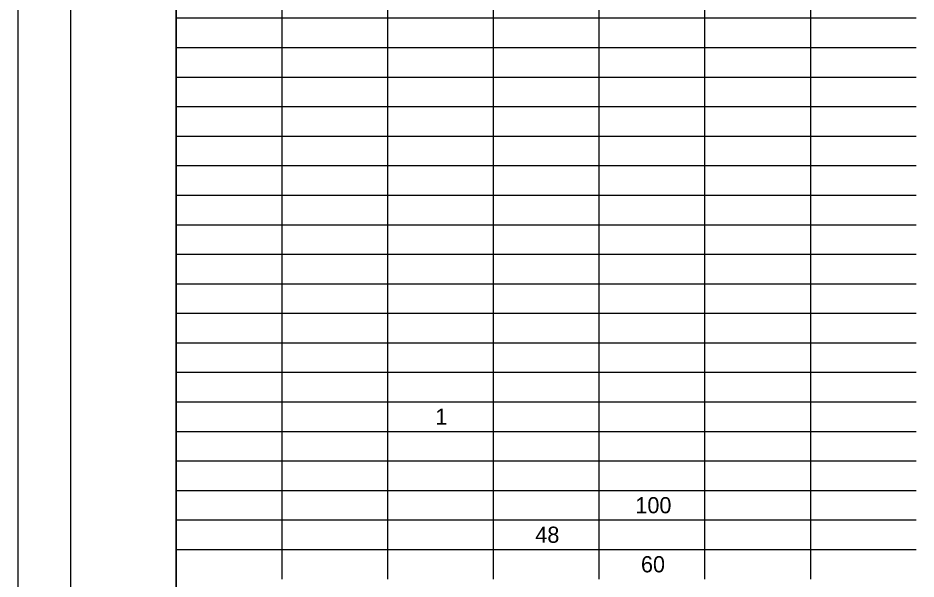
# Model space of a CAD drawing. Extents: x 0 to 34, y 0 to 22.
# Drawn here: x 0 to 8.52, y 11.42 to 16.74 of the extents above; entities that cross this region are included whole.
import ezdxf

# ---------------------------------------------------------------- set-up
doc = ezdxf.new("R2010")
doc.units = 0
for name, color, linetype in [('SH_Border', 7, 'Continuous'), ('SH_Cut_Line', 7, 'Continuous'), ('SH_Text', 7, 'Continuous')]:
    doc.layers.add(name, color=color, linetype=linetype)

msp = doc.modelspace()

# ---------------------------------------------------------------- linework, layer by layer
at = {"layer": 'SH_Border'}
for points in [[(0.5, 21.5), (1.5, 21.5), (1.5, 0.5), (0.5, 0.5)], [(1.5, 21.5), (33.5, 21.5), (33.5, 0.5), (1.5, 0.5)]]:
    msp.add_lwpolyline(points, close=True, dxfattribs=at)
at = {"layer": 'SH_Cut_Line'}
msp.add_lwpolyline([(0, 0), (34, 0), (34, 22), (0, 22)], close=True, dxfattribs=at)
at = {"layer": 'SH_Text'}
for p, q in [((1.5, 17.0199), (1.5, 16.7399)), ((2.5027, 17.0199), (2.5027, 16.7399)), ((3.5053, 17.0199), (3.5053, 16.7399)), ((4.508, 17.0199), (4.508, 16.7399)), ((5.5106, 17.0199), (5.5106, 16.7399)), ((6.5133, 17.0199), (6.5133, 16.7399)), ((7.516, 17.0199), (7.516, 16.7399)), ((1.5, 16.7399), (2.5027, 16.7399)), ((1.5, 16.7399), (1.5, 16.1799)), ((2.5027, 16.7399), (3.5053, 16.7399)), ((2.5027, 16.7399), (2.5027, 16.1799)), ((3.5053, 16.7399), (4.508, 16.7399)), ((3.5053, 16.7399), (3.5053, 16.1799)), ((4.508, 16.7399), (5.5106, 16.7399)), ((4.508, 16.7399), (4.508, 16.1799)), ((5.5106, 16.7399), (6.5133, 16.7399)), ((5.5106, 16.7399), (5.5106, 16.1799)), ((6.5133, 16.7399), (7.516, 16.7399)), ((6.5133, 16.7399), (6.5133, 16.1799)), ((7.516, 16.7399), (8.5186, 16.7399)), ((7.516, 16.7399), (7.516, 16.1799)), ((1.5, 16.4599), (2.5027, 16.4599)), ((2.5027, 16.4599), (3.5053, 16.4599)), ((3.5053, 16.4599), (4.508, 16.4599)), ((4.508, 16.4599), (5.5106, 16.4599)), ((5.5106, 16.4599), (6.5133, 16.4599)), ((6.5133, 16.4599), (7.516, 16.4599)), ((7.516, 16.4599), (8.5186, 16.4599)), ((1.5, 16.1799), (2.5027, 16.1799)), ((1.5, 16.1799), (1.5, 15.8999)), ((2.5027, 16.1799), (3.5053, 16.1799)), ((2.5027, 16.1799), (2.5027, 15.8999)), ((3.5053, 16.1799), (4.508, 16.1799)), ((3.5053, 16.1799), (3.5053, 15.8999)), ((4.508, 16.1799), (5.5106, 16.1799)), ((4.508, 16.1799), (4.508, 15.8999)), ((5.5106, 16.1799), (6.5133, 16.1799)), ((5.5106, 16.1799), (5.5106, 15.8999)), ((6.5133, 16.1799), (7.516, 16.1799)), ((6.5133, 16.1799), (6.5133, 15.8999)), ((7.516, 16.1799), (8.5186, 16.1799)), ((7.516, 16.1799), (7.516, 15.8999)), ((1.5, 15.8999), (2.5027, 15.8999)), ((1.5, 15.8999), (1.5, 15.6198)), ((2.5027, 15.8999), (3.5053, 15.8999)), ((2.5027, 15.8999), (2.5027, 15.6198)), ((3.5053, 15.8999), (4.508, 15.8999)), ((3.5053, 15.8999), (3.5053, 15.6198)), ((4.508, 15.8999), (5.5106, 15.8999)), ((4.508, 15.8999), (4.508, 15.6198)), ((5.5106, 15.8999), (6.5133, 15.8999)), ((5.5106, 15.8999), (5.5106, 15.6198)), ((6.5133, 15.8999), (7.516, 15.8999)), ((6.5133, 15.8999), (6.5133, 15.6198)), ((7.516, 15.8999), (8.5186, 15.8999)), ((7.516, 15.8999), (7.516, 15.6198)), ((1.5, 15.6198), (2.5027, 15.6198)), ((1.5, 15.6198), (1.5, 15.3398)), ((2.5027, 15.6198), (3.5053, 15.6198)), ((2.5027, 15.6198), (2.5027, 15.3398)), ((3.5053, 15.6198), (4.508, 15.6198)), ((3.5053, 15.6198), (3.5053, 15.3398)), ((4.508, 15.6198), (5.5106, 15.6198)), ((4.508, 15.6198), (4.508, 15.3398)), ((5.5106, 15.6198), (6.5133, 15.6198)), ((5.5106, 15.6198), (5.5106, 15.3398)), ((6.5133, 15.6198), (7.516, 15.6198)), ((6.5133, 15.6198), (6.5133, 15.3398)), ((7.516, 15.6198), (8.5186, 15.6198)), ((7.516, 15.6198), (7.516, 15.3398)), ((1.5, 15.3398), (2.5027, 15.3398)), ((1.5, 15.3398), (1.5, 14.7798)), ((2.5027, 15.3398), (3.5053, 15.3398)), ((2.5027, 15.3398), (2.5027, 14.7798)), ((3.5053, 15.3398), (4.508, 15.3398)), ((3.5053, 15.3398), (3.5053, 14.7798)), ((4.508, 15.3398), (5.5106, 15.3398)), ((4.508, 15.3398), (4.508, 14.7798)), ((5.5106, 15.3398), (6.5133, 15.3398)), ((5.5106, 15.3398), (5.5106, 14.7798)), ((6.5133, 15.3398), (7.516, 15.3398)), ((6.5133, 15.3398), (6.5133, 14.7798)), ((7.516, 15.3398), (8.5186, 15.3398)), ((7.516, 15.3398), (7.516, 14.7798)), ((1.5, 15.0598), (2.5027, 15.0598)), ((2.5027, 15.0598), (3.5053, 15.0598)), ((3.5053, 15.0598), (4.508, 15.0598)), ((4.508, 15.0598), (5.5106, 15.0598)), ((5.5106, 15.0598), (6.5133, 15.0598)), ((6.5133, 15.0598), (7.516, 15.0598)), ((7.516, 15.0598), (8.5186, 15.0598)), ((1.5, 14.7798), (2.5027, 14.7798)), ((1.5, 14.7798), (1.5, 14.4998)), ((2.5027, 14.7798), (3.5053, 14.7798)), ((2.5027, 14.7798), (2.5027, 14.4998)), ((3.5053, 14.7798), (4.508, 14.7798)), ((3.5053, 14.7798), (3.5053, 14.4998)), ((4.508, 14.7798), (5.5106, 14.7798)), ((4.508, 14.7798), (4.508, 14.4998)), ((5.5106, 14.7798), (6.5133, 14.7798)), ((5.5106, 14.7798), (5.5106, 14.4998)), ((6.5133, 14.7798), (7.516, 14.7798)), ((6.5133, 14.7798), (6.5133, 14.4998)), ((7.516, 14.7798), (8.5186, 14.7798)), ((7.516, 14.7798), (7.516, 14.4998)), ((1.5, 14.4998), (2.5027, 14.4998)), ((1.5, 14.4998), (1.5, 14.2198)), ((2.5027, 14.4998), (3.5053, 14.4998)), ((2.5027, 14.4998), (2.5027, 14.2198)), ((3.5053, 14.4998), (4.508, 14.4998)), ((3.5053, 14.4998), (3.5053, 14.2198)), ((4.508, 14.4998), (5.5106, 14.4998)), ((4.508, 14.4998), (4.508, 14.2198)), ((5.5106, 14.4998), (6.5133, 14.4998)), ((5.5106, 14.4998), (5.5106, 14.2198)), ((6.5133, 14.4998), (7.516, 14.4998)), ((6.5133, 14.4998), (6.5133, 14.2198)), ((7.516, 14.4998), (8.5186, 14.4998)), ((7.516, 14.4998), (7.516, 14.2198)), ((1.5, 14.2198), (2.5027, 14.2198)), ((1.5, 14.2198), (1.5, 13.9398)), ((2.5027, 14.2198), (3.5053, 14.2198)), ((2.5027, 14.2198), (2.5027, 13.9398)), ((3.5053, 14.2198), (4.508, 14.2198)), ((3.5053, 14.2198), (3.5053, 13.9398)), ((4.508, 14.2198), (5.5106, 14.2198)), ((4.508, 14.2198), (4.508, 13.9398)), ((5.5106, 14.2198), (6.5133, 14.2198)), ((5.5106, 14.2198), (5.5106, 13.9398)), ((6.5133, 14.2198), (7.516, 14.2198)), ((6.5133, 14.2198), (6.5133, 13.9398)), ((7.516, 14.2198), (8.5186, 14.2198)), ((7.516, 14.2198), (7.516, 13.9398)), ((1.5, 13.9398), (2.5027, 13.9398)), ((1.5, 13.9398), (1.5, 11.6997)), ((2.5027, 13.9398), (3.5053, 13.9398)), ((2.5027, 13.9398), (2.5027, 11.6997)), ((3.5053, 13.9398), (4.508, 13.9398)), ((3.5053, 13.9398), (3.5053, 11.6997)), ((4.508, 13.9398), (5.5106, 13.9398)), ((4.508, 13.9398), (4.508, 11.6997)), ((5.5106, 13.9398), (6.5133, 13.9398)), ((5.5106, 13.9398), (5.5106, 11.6997)), ((6.5133, 13.9398), (7.516, 13.9398)), ((6.5133, 13.9398), (6.5133, 11.6997)), ((7.516, 13.9398), (8.5186, 13.9398)), ((7.516, 13.9398), (7.516, 11.6997)), ((1.5, 13.6598), (2.5027, 13.6598)), ((2.5027, 13.6598), (3.5053, 13.6598)), ((3.5053, 13.6598), (4.508, 13.6598)), ((4.508, 13.6598), (5.5106, 13.6598)), ((5.5106, 13.6598), (6.5133, 13.6598)), ((6.5133, 13.6598), (7.516, 13.6598)), ((7.516, 13.6598), (8.5186, 13.6598)), ((1.5, 13.3798), (2.5027, 13.3798)), ((2.5027, 13.3798), (3.5053, 13.3798)), ((3.5053, 13.3798), (4.508, 13.3798)), ((4.508, 13.3798), (5.5106, 13.3798)), ((5.5106, 13.3798), (6.5133, 13.3798)), ((6.5133, 13.3798), (7.516, 13.3798)), ((7.516, 13.3798), (8.5186, 13.3798)), ((1.5, 13.0998), (2.5027, 13.0998)), ((2.5027, 13.0998), (3.5053, 13.0998)), ((3.5053, 13.0998), (4.508, 13.0998)), ((4.508, 13.0998), (5.5106, 13.0998)), ((5.5106, 13.0998), (6.5133, 13.0998)), ((6.5133, 13.0998), (7.516, 13.0998)), ((7.516, 13.0998), (8.5186, 13.0998)), ((1.5, 12.8198), (2.5027, 12.8198)), ((2.5027, 12.8198), (3.5053, 12.8198)), ((3.5053, 12.8198), (4.508, 12.8198)), ((4.508, 12.8198), (5.5106, 12.8198)), ((5.5106, 12.8198), (6.5133, 12.8198)), ((6.5133, 12.8198), (7.516, 12.8198)), ((7.516, 12.8198), (8.5186, 12.8198)), ((1.5, 12.5398), (2.5027, 12.5398)), ((2.5027, 12.5398), (3.5053, 12.5398)), ((3.5053, 12.5398), (4.508, 12.5398)), ((4.508, 12.5398), (5.5106, 12.5398)), ((5.5106, 12.5398), (6.5133, 12.5398)), ((6.5133, 12.5398), (7.516, 12.5398)), ((7.516, 12.5398), (8.5186, 12.5398)), ((1.5, 12.2598), (2.5027, 12.2598)), ((2.5027, 12.2598), (3.5053, 12.2598)), ((3.5053, 12.2598), (4.508, 12.2598)), ((4.508, 12.2598), (5.5106, 12.2598)), ((5.5106, 12.2598), (6.5133, 12.2598)), ((6.5133, 12.2598), (7.516, 12.2598)), ((7.516, 12.2598), (8.5186, 12.2598)), ((1.5, 11.9798), (2.5027, 11.9798)), ((2.5027, 11.9798), (3.5053, 11.9798)), ((3.5053, 11.9798), (4.508, 11.9798)), ((4.508, 11.9798), (5.5106, 11.9798)), ((5.5106, 11.9798), (6.5133, 11.9798)), ((6.5133, 11.9798), (7.516, 11.9798)), ((7.516, 11.9798), (8.5186, 11.9798)), ((1.5, 11.6997), (2.5027, 11.6997)), ((1.5, 11.6997), (1.5, 11.4197)), ((2.5027, 11.6997), (3.5053, 11.6997)), ((2.5027, 11.6997), (2.5027, 11.4197)), ((3.5053, 11.6997), (4.508, 11.6997)), ((3.5053, 11.6997), (3.5053, 11.4197)), ((4.508, 11.6997), (5.5106, 11.6997)), ((4.508, 11.6997), (4.508, 11.4197)), ((5.5106, 11.6997), (6.5133, 11.6997)), ((5.5106, 11.6997), (5.5106, 11.4197)), ((6.5133, 11.6997), (7.516, 11.6997)), ((6.5133, 11.6997), (6.5133, 11.4197)), ((7.516, 11.6997), (8.5186, 11.6997)), ((7.516, 11.6997), (7.516, 11.4197))]:
    msp.add_line(p, q, dxfattribs=at)

# ---------------------------------------------------------------- texts
for s, height, p in [('1', 0.1533, (3.9592, 12.8831)), ('100', 0.15334, (5.8563, 12.0431)), ('48', 0.15334, (4.9074, 11.7631)), ('60', 0.15334, (5.9094, 11.4831))]:
    msp.add_text(s, height=height, dxfattribs=at).set_placement(p)

doc.saveas('drawing.dxf')
